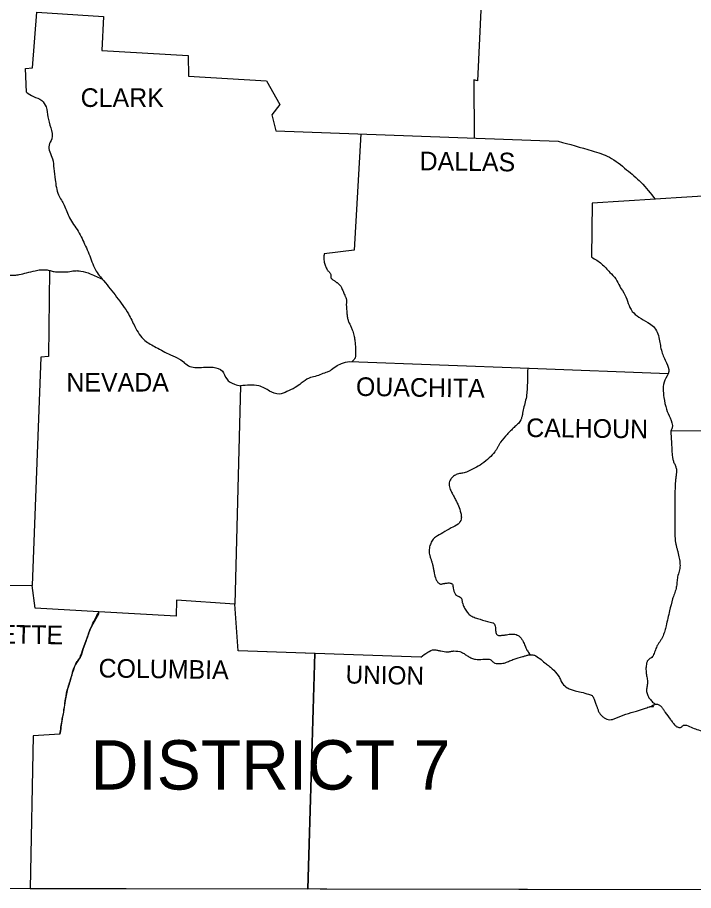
# Model space of a CAD drawing. Extents: x 164 to 3385, y 68 to 2119.
# Drawn here: x 2834.9 to 2985.9, y 1432.9 to 1627.9 of the extents above; entities that cross this region are included whole.
import ezdxf

# ---------------------------------------------------------------- set-up
doc = ezdxf.new("R2010")
doc.units = 0
for name, color, linetype in [('1', 7, 'Continuous'), ('Default', 7, 'Continuous'), ('S_MISC_BOUNDARY', 7, 'Continuous')]:
    doc.layers.add(name, color=color, linetype=linetype)

msp = doc.modelspace()

# ---------------------------------------------------------------- linework, layer by layer
at = {"layer": '1'}
for points in [[(2769.26, 1512.61), (2769.46, 1433.46), (3128.04, 1432.87)], [(2769.26, 1511.75), (2769.46, 1433.46), (3124.12, 1432.88)], [(2901.25, 1485.35), (2899.73, 1433.25)]]:
    msp.add_lwpolyline(points, dxfattribs=at)
at = {"layer": 'Default'}
for points in [[(2938.8, 1639.1), (2937.64, 1613.74), (2936.77, 1614.03), (2936.87, 1600.98)], [(2836.9, 1611.23), (2836.71, 1616.55), (2838.26, 1616.65), (2839.23, 1629.13), (2854.13, 1628.16), (2853.74, 1620.52), (2873, 1619.45), (2873.1, 1614.81), (2890.51, 1613.74), (2893.51, 1608.52), (2891.68, 1606.2), (2892.55, 1602.62), (2955.64, 1600.29)], [(2911.58, 1601.91), (2910.06, 1575.91), (2903.39, 1575.13)], [(2991.45, 1588.2), (2977.3, 1587.32)], [(2977.35, 1587.33), (2963.19, 1586.45), (2963.09, 1574.36)], [(2842.03, 1571.41), (2841.84, 1552.2), (2840.1, 1552), (2838.16, 1501.01)], [(2909.09, 1551.04), (2949.16, 1549.59), (2980.23, 1548.37)], [(2884.71, 1545.62), (2883.45, 1496.84), (2870.39, 1497.72), (2870.29, 1494.14), (2853.07, 1495.14)], [(2980.8, 1535.55), (3024.54, 1535.65)], [(2769.26, 1511.75), (2769.46, 1433.46), (3124.12, 1432.88)], [(2838.16, 1501.01), (2808.84, 1500.72)], [(2853.07, 1495.14), (2838.84, 1495.97), (2838.16, 1501.01)], [(2924.96, 1485.04), (2884.18, 1486.43), (2883.45, 1496.84)], [(2901.26, 1485.93), (2899.73, 1433.25)], [(2844.36, 1467.81), (2838.36, 1467.43), (2837.7, 1433.35)]]:
    msp.add_lwpolyline(points, dxfattribs=at)
for points in [[(2836.9, 1611.23), (2838.45, 1610.26), (2840.29, 1609.39), (2841.26, 1607.94), (2841.65, 1605.71), (2842.32, 1603.29), (2842.52, 1600.78), (2841.94, 1599.42), (2842.71, 1596.33), (2843, 1594.2), (2843.29, 1591.68), (2844.07, 1588.29), (2845.32, 1585.97), (2846.48, 1583.16), (2848.42, 1580.16), (2850.07, 1576.87), (2850.84, 1575.13), (2852.29, 1571.55), (2854.13, 1569.13), (2857.03, 1565.46), (2859.65, 1561.68), (2861.1, 1558.88), (2863.32, 1555.78), (2865.84, 1554.23), (2869.03, 1552.58), (2871.06, 1551.62), (2873.39, 1549.97), (2876.39, 1549.78), (2878.61, 1549.78), (2880.64, 1548.91), (2881.61, 1547.17), (2883.35, 1546), (2884.71, 1545.62)], [(2955.64, 1600.29), (2963.19, 1598.16), (2967.06, 1596.71), (2970.93, 1593.91), (2974.12, 1591.1), (2977.3, 1587.32)], [(2797.29, 1579.19), (2801.39, 1578.81), (2804.78, 1578.42), (2806.09, 1578.32), (2806.74, 1578.25), (2807.07, 1578.2), (2807.39, 1578.13), (2808.08, 1577.93), (2808.76, 1577.68), (2810.1, 1577.16), (2812.52, 1576.29), (2812.91, 1576.13), (2813.29, 1575.95), (2813.67, 1575.77), (2814.07, 1575.62), (2814.71, 1575.55), (2815.37, 1575.66), (2816.03, 1575.8), (2816.68, 1575.81), (2817.79, 1575.6), (2818.91, 1575.33), (2820.19, 1574.98), (2820.82, 1574.76), (2821.12, 1574.62), (2821.42, 1574.46), (2822.39, 1573.68), (2823.26, 1572.81), (2823.54, 1572.5), (2823.79, 1572.17), (2824.42, 1571.55), (2824.96, 1571.26), (2825.52, 1571.11), (2826.65, 1571.07), (2827.11, 1571.12), (2827.57, 1571.22), (2828.03, 1571.32), (2828.49, 1571.36), (2830.71, 1571.16), (2831.35, 1570.99), (2831.97, 1570.76), (2832.59, 1570.53), (2833.23, 1570.39), (2833.73, 1570.35), (2834.25, 1570.35), (2835.26, 1570.49), (2836.9, 1570.87), (2838.84, 1571.36), (2840.05, 1571.55), (2840.66, 1571.57), (2841.26, 1571.55), (2841.72, 1571.48), (2842.18, 1571.37), (2842.63, 1571.25), (2843.1, 1571.16), (2844.31, 1571.09), (2845.52, 1571.07), (2846.22, 1571.12), (2846.92, 1571.24), (2847.62, 1571.34), (2847.97, 1571.36), (2848.32, 1571.36), (2849.04, 1571.27), (2851.15, 1570.66), (2852.52, 1570.07), (2853.87, 1569.46)], [(2903.39, 1575.13), (2903.28, 1574.22), (2903.31, 1573.75), (2903.39, 1573.29), (2903.5, 1572.84), (2903.66, 1572.4), (2903.84, 1571.97), (2904.06, 1571.55), (2904.22, 1571.34), (2904.4, 1571.16), (2904.58, 1570.97), (2904.74, 1570.78), (2904.84, 1570.48), (2904.85, 1570.13), (2904.89, 1569.79), (2904.94, 1569.65), (2905.03, 1569.52), (2905.23, 1569.36), (2905.46, 1569.22), (2905.69, 1569.09), (2905.9, 1568.94), (2906.07, 1568.81), (2906.25, 1568.68), (2906.59, 1568.42), (2906.91, 1568.13), (2907.05, 1567.96), (2907.16, 1567.78), (2907.35, 1567.37), (2907.51, 1566.96), (2907.67, 1566.54), (2907.84, 1566.13), (2908.1, 1565.61), (2908.22, 1565.35), (2908.27, 1565.21), (2908.32, 1565.07), (2908.37, 1564.73), (2908.36, 1564.39), (2908.33, 1564.05), (2908.32, 1563.71), (2908.37, 1563.04), (2908.42, 1562.36), (2908.49, 1561.53), (2908.54, 1561.12), (2908.61, 1560.71), (2908.83, 1559.97), (2909.16, 1559.25), (2909.5, 1558.54), (2909.77, 1557.81), (2910.06, 1556.65), (2910.26, 1555.68), (2910.35, 1554.04), (2910.37, 1553.55), (2910.38, 1553.07), (2910.37, 1552.58), (2910.36, 1552.34), (2910.35, 1552.1), (2910.27, 1551.83), (2910.08, 1551.53), (2909.55, 1551.02)], [(2963.09, 1574.36), (2965.32, 1572.91), (2967.16, 1570.97), (2968.51, 1569.52), (2969.38, 1567.87), (2970.54, 1565.94), (2972.19, 1562.26), (2973.64, 1561), (2975.67, 1559.75), (2976.93, 1558.88), (2978.19, 1556.07), (2978.77, 1553.26), (2979.83, 1550.75), (2980.32, 1548.81), (2979.45, 1546.88), (2979.25, 1543), (2979.83, 1540.39), (2980.61, 1538.46), (2981.09, 1536.23), (2980.8, 1535.55)], [(2904.74, 1549), (2907.26, 1550.65), (2909.09, 1551.04)], [(2904.74, 1549), (2904.04, 1548.72), (2902.8, 1548.23), (2901.35, 1547.75), (2900, 1547.36), (2898.26, 1546.2), (2896.9, 1545.23), (2895.06, 1544.36), (2893.32, 1543.78), (2891.19, 1544.46), (2890.03, 1545.13), (2888.77, 1545.62), (2884.71, 1545.62)], [(2948.83, 1549.6), (2948.77, 1546.59), (2948.7, 1545.09), (2948.65, 1544.34), (2948.58, 1543.59), (2948.28, 1542.08), (2947.9, 1540.59), (2947.64, 1539.21), (2947.48, 1538.53), (2947.36, 1538.2), (2947.3, 1538.04), (2947.22, 1537.88), (2946.93, 1537.43), (2946.56, 1537.05), (2945.77, 1536.33), (2944.99, 1535.56), (2944.22, 1534.78), (2942.77, 1533.04), (2942.43, 1532.52), (2942.14, 1531.97), (2941.85, 1531.43), (2941.51, 1530.91), (2940.25, 1529.55), (2938.61, 1528.2), (2936.96, 1527.23), (2935.13, 1526.36), (2934.63, 1526.2), (2934.12, 1526.11), (2933.6, 1526.02), (2933.09, 1525.88), (2932.29, 1525.47), (2931.94, 1525.18), (2931.79, 1525.01), (2931.64, 1524.81), (2931.38, 1524.25), (2931.3, 1523.65), (2931.55, 1522.49), (2931.94, 1521.67), (2932.37, 1520.85), (2932.8, 1520.03), (2933.19, 1519.2), (2933.77, 1517.65), (2933.9, 1517.2), (2933.98, 1516.74), (2934.01, 1516.27), (2933.96, 1515.81), (2933.29, 1514.75), (2931.74, 1513.88), (2929.9, 1512.81), (2928.25, 1511.84), (2927.86, 1511.53), (2927.55, 1511.14), (2927.3, 1510.68), (2927.09, 1510.2), (2926.83, 1509.08), (2926.9, 1507.97), (2927.08, 1507.32), (2927.29, 1506.67), (2927.49, 1506.02), (2927.67, 1505.36), (2927.82, 1504.59), (2927.96, 1503.81), (2928.33, 1502.44), (2928.68, 1501.84), (2928.92, 1501.59), (2929.06, 1501.49), (2929.22, 1501.39), (2929.46, 1501.34), (2929.71, 1501.38), (2929.95, 1501.45), (2930.19, 1501.49), (2930.41, 1501.51), (2930.63, 1501.54), (2931.06, 1501.6), (2931.5, 1501.58), (2931.72, 1501.52), (2931.82, 1501.46), (2931.93, 1501.39), (2932.08, 1501.17), (2932.13, 1500.91), (2932.22, 1500.43), (2932.61, 1499.17), (2932.9, 1498.84), (2933.33, 1498.63), (2933.77, 1498.42), (2934.06, 1498.1), (2934.13, 1497.87), (2934.16, 1497.62), (2934.19, 1497.37), (2934.25, 1497.14), (2934.62, 1496.2), (2935.13, 1495.3), (2935.43, 1494.9), (2935.77, 1494.56), (2936.58, 1494.04), (2937.64, 1493.65), (2939.87, 1492.97), (2941.03, 1492.68), (2941.19, 1492.61), (2941.5, 1492.14), (2941.65, 1491.2), (2941.8, 1490.31), (2941.98, 1490.01), (2942.29, 1489.88), (2943.06, 1489.89), (2943.83, 1489.97), (2945, 1490.17), (2945.97, 1490.12), (2946.46, 1489.96), (2946.7, 1489.84), (2946.93, 1489.68), (2947.45, 1489.14), (2947.8, 1488.52), (2948.03, 1488.04), (2948.24, 1487.56), (2948.44, 1487.07), (2948.67, 1486.59), (2949.18, 1485.85), (2949.46, 1485.56)], [(2980.8, 1535.55), (2980.87, 1534.05), (2980.97, 1532.55), (2981.19, 1529.55), (2981.36, 1528.82), (2981.66, 1528.1), (2981.94, 1527.39), (2982.03, 1527.02), (2982.06, 1526.65), (2982.01, 1525.88), (2981.92, 1525.1), (2981.83, 1524.33), (2981.77, 1523.55), (2981.67, 1520.55), (2981.67, 1517.84), (2981.67, 1515.23), (2981.67, 1512.52), (2981.87, 1510.59), (2982.01, 1509.88), (2982.19, 1509.18), (2982.38, 1508.48), (2982.54, 1507.78), (2982.78, 1506.47), (2982.84, 1505.82), (2982.83, 1505.17), (2982.73, 1504.54), (2982.57, 1503.91), (2982.39, 1503.28), (2982.25, 1502.65), (2982.18, 1502.07), (2982.13, 1501.49), (2982.07, 1500.9), (2981.96, 1500.33), (2981.79, 1499.74), (2981.58, 1499.17), (2981.37, 1498.59), (2981.19, 1498.01), (2980.51, 1495.39), (2979.74, 1492.01), (2979.44, 1490.88), (2979.26, 1490.33), (2979.06, 1489.78), (2978.77, 1489.18), (2978.41, 1488.6), (2978.04, 1488.04), (2977.7, 1487.46), (2977.47, 1486.94), (2977.26, 1486.4), (2977.06, 1485.85), (2976.83, 1485.33), (2976.53, 1484.97), (2976.13, 1484.68), (2975.74, 1484.37), (2975.59, 1484.19), (2975.48, 1483.97), (2975.26, 1482.81), (2975.28, 1481.65), (2975.35, 1481.12), (2975.43, 1480.59), (2975.52, 1480.06), (2975.58, 1479.52), (2975.56, 1479.04), (2975.48, 1478.56), (2975.4, 1478.07), (2975.38, 1477.59), (2975.56, 1476.65), (2976.06, 1475.75), (2976.38, 1475.35), (2976.73, 1474.98), (2977.44, 1474.49)], [(2844.36, 1467.81), (2844.84, 1470.91), (2844.95, 1471.52), (2845.08, 1472.12), (2845.21, 1472.72), (2845.23, 1473.29), (2845.41, 1473.91), (2845.47, 1474.49), (2845.53, 1475.07), (2845.61, 1475.65), (2846.19, 1478.26), (2847.07, 1481.07), (2847.84, 1483.39), (2847.94, 1483.62), (2848.07, 1483.82), (2848.37, 1484.22), (2848.67, 1484.61), (2848.8, 1484.82), (2848.9, 1485.04), (2849.08, 1485.52), (2849.24, 1486.01), (2849.41, 1486.49), (2849.58, 1486.97), (2850.45, 1489.3), (2850.66, 1489.91), (2850.85, 1490.52), (2851.06, 1491.13), (2851.32, 1491.72), (2853.07, 1495.14)], [(2924.96, 1485.04), (2926.51, 1486.1), (2927.96, 1486.68), (2928.69, 1486.56), (2929.05, 1486.47), (2929.42, 1486.39), (2930.96, 1486.2), (2931.3, 1486.22), (2931.64, 1486.28), (2931.98, 1486.36), (2932.32, 1486.39), (2934.06, 1486.1), (2934.45, 1485.91), (2934.8, 1485.68), (2935.15, 1485.44), (2935.51, 1485.23), (2936.31, 1484.79), (2937.16, 1484.55), (2938.8, 1484.55), (2940.25, 1484.55), (2940.6, 1484.43), (2940.89, 1484.15), (2941.18, 1483.86), (2941.51, 1483.68), (2942.08, 1483.6), (2942.68, 1483.58), (2943.27, 1483.64), (2943.83, 1483.78), (2944.32, 1483.97), (2944.8, 1484.17), (2945.28, 1484.37), (2945.77, 1484.55), (2947.71, 1485.14), (2948.36, 1485.33), (2949.03, 1485.5), (2949.69, 1485.56), (2950.01, 1485.53), (2950.32, 1485.43), (2951.52, 1484.68), (2952.64, 1483.78), (2953.47, 1483.12), (2954.29, 1482.43), (2955.64, 1480.88), (2955.9, 1480.46), (2956.12, 1480.01), (2956.34, 1479.56), (2956.61, 1479.14), (2957.67, 1478.17), (2958.1, 1477.95), (2958.53, 1477.77), (2959.41, 1477.49), (2960.77, 1477.2), (2962.41, 1476.72), (2962.88, 1476.59), (2963.1, 1476.49), (2963.29, 1476.33), (2963.56, 1475.89), (2963.74, 1475.43), (2963.89, 1474.96), (2964.06, 1474.49), (2964.19, 1474.17), (2964.31, 1473.85), (2964.53, 1473.22), (2964.83, 1472.59), (2965.04, 1472.28), (2965.17, 1472.13), (2965.32, 1471.97), (2965.9, 1471.49), (2966.51, 1471.17), (2967.13, 1471.04), (2967.74, 1471.1), (2968.49, 1471.36), (2969.23, 1471.68), (2969.98, 1472), (2970.74, 1472.27), (2973.16, 1472.94), (2974.9, 1473.52), (2975.96, 1473.91), (2976.2, 1473.96), (2976.45, 1473.96), (2976.69, 1473.97), (2976.93, 1474.01), (2976.94, 1474.02), (2976.92, 1474.04), (2976.79, 1474.1), (2976.66, 1474.15), (2976.63, 1474.18), (2976.64, 1474.2), (2976.91, 1474.33), (2977.22, 1474.44), (2977.8, 1474.49), (2978.08, 1474.38), (2978.37, 1474.21), (2978.87, 1473.72), (2979.04, 1473.45), (2979.21, 1473.18), (2979.37, 1472.91), (2979.54, 1472.65), (2980.7, 1471.1), (2981.21, 1470.42), (2981.48, 1470.09), (2981.77, 1469.75), (2982, 1469.55), (2982.28, 1469.41), (2982.56, 1469.32), (2982.83, 1469.27), (2983.1, 1469.35), (2983.36, 1469.58), (2983.62, 1469.8), (2983.9, 1469.85), (2985.35, 1469.36), (2986.61, 1468.88), (2988.06, 1468.49), (2988.37, 1468.45), (2988.69, 1468.44), (2989, 1468.42), (2989.32, 1468.39), (2990.96, 1468.01), (2992.22, 1467.33), (2993.38, 1466.65), (2994.54, 1465.39), (2995.7, 1463.46), (2995.83, 1463.09), (2995.9, 1462.69), (2995.97, 1462.3), (2996.09, 1461.91), (2996.66, 1461.05), (2997.03, 1460.68), (2997.45, 1460.36), (2997.75, 1460.3), (2998.11, 1460.39), (2998.45, 1460.47), (2998.7, 1460.36), (2999.17, 1459.74), (2999.64, 1459.11), (3000.54, 1457.85), (3001.22, 1456.88), (3001.85, 1455.95), (3002.21, 1455.51), (3002.43, 1455.32), (3002.67, 1455.14), (3002.93, 1455.06), (3003.2, 1455.08), (3003.47, 1455.13), (3003.74, 1455.14), (3005.8, 1454.74)]]:
    msp.add_spline(points, degree=3, dxfattribs=at)
at = {"layer": 'S_MISC_BOUNDARY'}
for p, q in [((2853.07, 1494.75), (2851.32, 1491.72)), ((2853.07, 1495.14), (2852.2, 1493.43)), ((2852.2, 1493.43), (2853.07, 1494.75)), ((2899.73, 1433.25), (2901.26, 1485.85)), ((2901.25, 1485.35), (2901.25, 1485.35)), ((2901.26, 1485.85), (2901.26, 1485.85)), ((2837.72, 1433.35), (2899.73, 1433.25))]:
    msp.add_line(p, q, dxfattribs=at)
for points in [[(2883.45, 1496.84), (2870.39, 1497.72), (2870.29, 1494.14), (2853.07, 1495.14)], [(2901.26, 1485.85), (2884.18, 1486.43), (2883.45, 1496.84)], [(2844.36, 1467.81), (2838.36, 1467.43), (2837.72, 1433.35)]]:
    msp.add_lwpolyline(points, dxfattribs=at)
msp.add_spline([(2851.32, 1491.72), (2850.96, 1490.83), (2850.02, 1488.14), (2849.58, 1486.97), (2848.85, 1484.93), (2847.84, 1483.39), (2846.63, 1479.67), (2846.19, 1478.26), (2845.57, 1475.36), (2844.89, 1471.21), (2844.6, 1469.36), (2844.36, 1467.81)], degree=3, dxfattribs=at)

# ---------------------------------------------------------------- texts
at = {"layer": 'Default'}
for s, height, p in [('CLARK', 4.161, (2849, 1607.94)), ('NEVADA', 4.161, (2845.81, 1544.36)), ('DISTRICT 7', 11.032, (2851.23, 1455.43))]:
    msp.add_text(s, height=height, dxfattribs=at).set_placement(p)
for s, height, rotation, p in [('DALLAS', 4.161, 359.2461, (2924.67, 1593.81)), ('OUACHITA', 4.162, 359.2043, (2910.45, 1543.39)), ('CALHOUN', 4.162, 359.3634, (2948.48, 1534.2)), ('LAFAYETTE', 4.161, 359.1839, (2813.2, 1488.33)), ('COLUMBIA', 4.161, 359.2125, (2852.97, 1480.49)), ('UNION', 4.065, 358.9584, (2908.13, 1479.14))]:
    msp.add_text(s, height=height, rotation=rotation, dxfattribs=at).set_placement(p)

doc.saveas('drawing.dxf')
